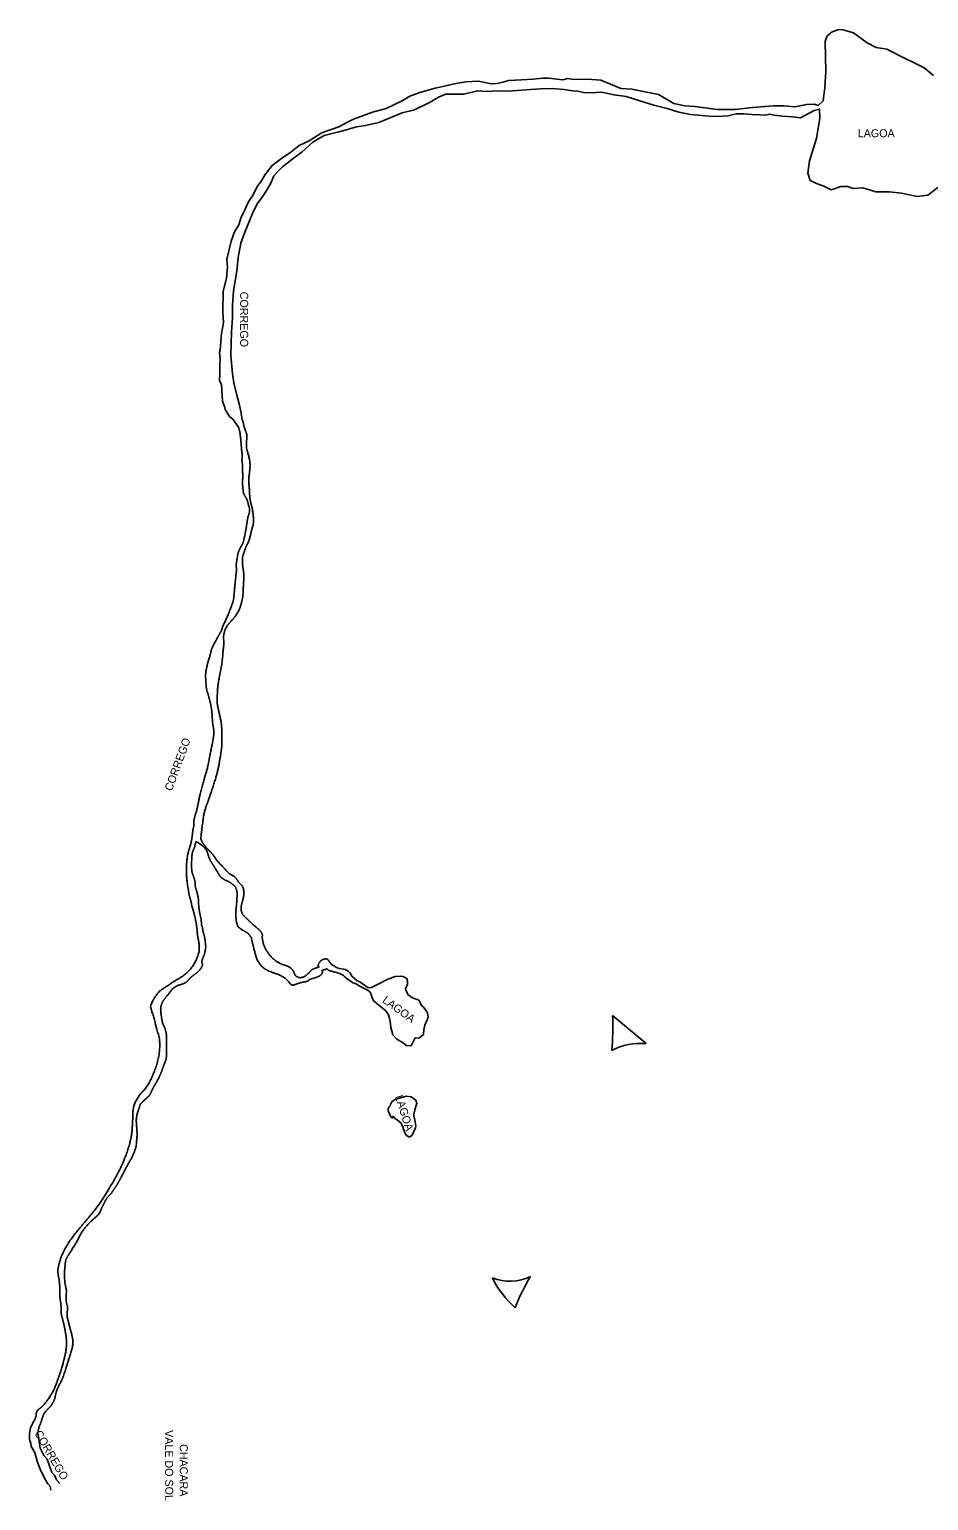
# Model space of a CAD drawing. Extents: x 325899 to 363134, y 7578590 to 7592502.
# Drawn here: x 347127 to 347576, y 7586466 to 7587201 of the extents above; entities that cross this region are included whole.
import ezdxf

# ---------------------------------------------------------------- set-up
doc = ezdxf.new("R2010")
doc.units = 0
for name, color, linetype in [('EDIFIDENTIF', 7, 'Continuous'), ('EDIFOBRAEXIS', 7, 'Continuous'), ('EDIFOBRAPROJ', 7, 'Continuous')]:
    doc.layers.add(name, color=color, linetype=linetype)

msp = doc.modelspace()

# ---------------------------------------------------------------- linework, layer by layer
at = {"layer": 'EDIFOBRAEXIS'}
for points in [[(347281.39, 7587152.06), (347285.49, 7587154.24), (347288.85, 7587155.9), (347293.86, 7587157.71), (347298.22, 7587159.38), (347305.14, 7587161.14), (347313.05, 7587164.99), (347316.99, 7587167.39), (347322, 7587169.2), (347329.52, 7587171.35), (347334.93, 7587172.53), (347339.93, 7587173.73), (347344.89, 7587174.53), (347351.28, 7587174.85), (347357.64, 7587173.44), (347360.4, 7587173.73), (347363.48, 7587174.25), (347366.41, 7587175.1), (347372.7, 7587175.49), (347378.41, 7587175.75), (347383.32, 7587176.26), (347386.29, 7587176.35), (347393.39, 7587175.57), (347395.92, 7587176.16), (347398.88, 7587175.71), (347405.63, 7587175.84), (347412.37, 7587175.25), (347417.21, 7587173.4), (347422.29, 7587171.15), (347427.8, 7587170.91), (347441.22, 7587168.16), (347443.97, 7587166.52), (347448.78, 7587163.71), (347454.42, 7587162.51), (347459.35, 7587162.16), (347470.66, 7587160.63), (347479.27, 7587160.67), (347488.24, 7587161.65), (347498.5, 7587162.46), (347503.96, 7587162.58), (347509.35, 7587162.04), (347515.15, 7587163.16), (347518.93, 7587163.27), (347521, 7587162.68), (347523.48, 7587165.04), (347524.35, 7587171.66), (347524.78, 7587179.87), (347524.63, 7587186.88), (347524.46, 7587194.7), (347525.41, 7587197.46), (347527.98, 7587199.45), (347531.31, 7587200.69), (347533.42, 7587200.46), (347538.66, 7587198.94), (347545.45, 7587193.99), (347549.89, 7587191.7), (347555.22, 7587190.9), (347563.74, 7587186.52), (347568.52, 7587184.14), (347573.98, 7587181.49), (347578.51, 7587177.73)], [(347580.68, 7587121.76), (347575.81, 7587117.79), (347570.42, 7587117.19), (347562.66, 7587118.82), (347556.35, 7587119.47), (347549.8, 7587119.46), (347543.21, 7587121.5), (347538.46, 7587121.26), (347535.83, 7587122.15), (347532.2, 7587122.14), (347527.43, 7587120.49), (347523.73, 7587122.39), (347520.1, 7587123.63), (347516.92, 7587125.18), (347515.8, 7587128.89), (347516.63, 7587135.03), (347520.17, 7587146.1), (347521.23, 7587153.39), (347521.87, 7587156.35), (347521.62, 7587160.89), (347518.99, 7587160.14), (347512.12, 7587156.46), (347508.22, 7587157.04), (347503.16, 7587157.33), (347498.91, 7587157.88), (347496.79, 7587158.26), (347494.57, 7587157.86), (347491.8, 7587157.97), (347487.86, 7587158.17), (347483.84, 7587158.56), (347480, 7587158.43), (347476.06, 7587157.53), (347473.12, 7587157.31), (347467.97, 7587157.25), (347462.78, 7587157.74), (347457.13, 7587158.25), (347451.39, 7587159.29), (347445.43, 7587161.17), (347438.85, 7587162.78), (347432.28, 7587164.77), (347425.09, 7587167.12), (347418.95, 7587167.98), (347412.73, 7587169.31), (347407, 7587169.01), (347403.69, 7587169.09), (347400.94, 7587169.77), (347398.41, 7587170.07), (347393.96, 7587170.68), (347388.26, 7587171.24), (347382.17, 7587170.98), (347377.25, 7587170.62), (347366.07, 7587169.81), (347360.78, 7587170.05), (347355.43, 7587169.63), (347350.81, 7587169.93), (347343.86, 7587168.39), (347334.97, 7587168.27), (347331.6, 7587166.97), (347326.73, 7587164.15), (347319.22, 7587160.56), (347313.08, 7587159.03), (347301.48, 7587154.15), (347294.84, 7587152.61), (347290.28, 7587151.97), (347288.55, 7587151.54), (347286.77, 7587151.03), (347285.97, 7587150.74), (347281.39, 7587149.51)], [(347281.39, 7587152.06), (347273.73, 7587149.29), (347272.58, 7587148.78), (347269.03, 7587146.44), (347266.61, 7587145.08), (347261.64, 7587142.65), (347257.48, 7587139.43), (347252.89, 7587136.2), (347248.19, 7587132.67), (347244.59, 7587128.26), (347242.46, 7587124.48), (347240.74, 7587122.16), (347238.46, 7587117.76), (347236.48, 7587114.85), (347234.95, 7587111.7), (347233.95, 7587109.39), (347232.62, 7587106.87), (347231.5, 7587103.05), (347229.3, 7587099.55), (347227.63, 7587094.81), (347225.5, 7587085.95), (347225.76, 7587081.9), (347225.38, 7587076.36), (347223.74, 7587069.96), (347223.71, 7587067.65), (347223.5, 7587061.42), (347223.49, 7587059.62), (347223.87, 7587054.05), (347222.85, 7587048.79), (347222.69, 7587047.09), (347222.43, 7587044.65), (347222.18, 7587040.64), (347221.79, 7587039.42), (347222.16, 7587035.98), (347222.02, 7587033.21), (347221.94, 7587028.46), (347221.83, 7587025.28), (347222.81, 7587023.07), (347223.35, 7587014.85), (347224.56, 7587011.67)], [(347234.23, 7587001.91), (347233.68, 7587004.43), (347233.15, 7587005.7), (347232.53, 7587009.72), (347231.63, 7587013.62), (347230.46, 7587017.95), (347229.02, 7587024.05), (347228.35, 7587028.58), (347227.45, 7587037.74), (347227.84, 7587049.58), (347228.28, 7587056.52), (347228.31, 7587062.8), (347228.9, 7587070.02), (347230.48, 7587079.87), (347231.25, 7587086.63), (347232.55, 7587093.87), (347234.54, 7587099.3), (347237.21, 7587105.87), (347238.91, 7587109.91), (347241.04, 7587113.99), (347242.37, 7587115.63), (347243.8, 7587117.79), (347244.88, 7587119.44), (347247.52, 7587123.82), (347249.06, 7587127.52), (347251.31, 7587130.06), (347253.3, 7587132.05), (347258.69, 7587136.22), (347263.12, 7587139.56), (347268.54, 7587144.34), (347271.78, 7587146.41), (347273.3, 7587147.24), (347274.2, 7587147.67), (347278.88, 7587148.86), (347281.39, 7587149.51)], [(347224.56, 7587011.67), (347224.69, 7587010.66), (347224.96, 7587010.17), (347226.45, 7587007.8), (347226.9, 7587007.23), (347228.64, 7587005.79), (347231.33, 7587001.91)], [(347281.39, 7586731.39), (347283.81, 7586731.13), (347284.6, 7586730.93), (347285.22, 7586730.62), (347286.1, 7586730.09), (347287.06, 7586729.09), (347288.03, 7586727.63), (347290.68, 7586725.23), (347292.01, 7586724.68), (347294.35, 7586723.08), (347296.17, 7586721.74), (347297.86, 7586721.97), (347300.46, 7586723.32), (347305.57, 7586725.89), (347309.69, 7586727.34), (347312.48, 7586727.53), (347313.6, 7586727.46), (347315.64, 7586726.23), (347315.66, 7586725.55), (347315.83, 7586725.15), (347315.84, 7586723.95), (347315.85, 7586723.5), (347315.5, 7586722.75), (347314.83, 7586721.18), (347315, 7586720.62), (347315.44, 7586719.7), (347315.96, 7586718.37), (347317.94, 7586716.98), (347319.07, 7586716.33), (347320.58, 7586715.95), (347321.36, 7586715.51), (347322.99, 7586712.77), (347323.88, 7586711.96), (347325.72, 7586709.25), (347326.04, 7586707.05), (347325.65, 7586705.71), (347324.44, 7586703.13), (347323.97, 7586700.96), (347323.75, 7586698.36), (347321.41, 7586696.61), (347319.66, 7586696.79), (347317.6, 7586692.76), (347315.23, 7586692.97), (347313.23, 7586694.35), (347310.38, 7586696.17), (347308.43, 7586698.32), (347307.43, 7586701.84), (347307.03, 7586704.96), (347306.81, 7586706.45), (347306.34, 7586708.31), (347304.96, 7586710.2), (347301.34, 7586713.21), (347298.84, 7586715.17), (347297.94, 7586717.17), (347297.69, 7586718.48), (347297.5, 7586719.06), (347296.37, 7586720.22), (347294.79, 7586721.14), (347291.36, 7586722.96), (347290.47, 7586723.57), (347288.67, 7586724.3), (347285.77, 7586726.12), (347284.45, 7586727.21), (347283.76, 7586727.94), (347282.97, 7586728.42), (347281.39, 7586729.01)], [(347318.15, 7586648.09), (347318.15, 7586648.09), (347318.15, 7586648.09), (347316.83, 7586647.16), (347315.31, 7586647.88), (347314.59, 7586648.97), (347314.15, 7586650.2), (347313.65, 7586651.48), (347313.53, 7586652.06), (347313.18, 7586652.77), (347312.63, 7586654.09), (347310.62, 7586655.86), (347309.4, 7586656.51), (347308.53, 7586657.6), (347308.08, 7586656.59), (347307.5, 7586657.24), (347306.19, 7586660.3), (347306.16, 7586661.23), (347306.66, 7586662.22), (347307.15, 7586662.82), (347307.31, 7586663.38), (347307.87, 7586664.79), (347308.57, 7586665.2), (347309.34, 7586665.73), (347311.15, 7586666.39), (347314.02, 7586667.3), (347315.11, 7586667.53), (347317.68, 7586667.26), (347319.94, 7586665.58), (347320.48, 7586663.94), (347320.05, 7586662.94), (347319.43, 7586660.83), (347318.96, 7586658.66), (347318.97, 7586657.72), (347319.39, 7586655.55), (347319.64, 7586654.82), (347319.86, 7586652.85), (347319.73, 7586651.85), (347318.15, 7586648.09)], [(347127.36, 7586501.91), (347126.94, 7586499.08), (347126.87, 7586498.07), (347126.9, 7586497.65), (347126.95, 7586496.05), (347127.19, 7586495.01), (347127.56, 7586494.1), (347127.79, 7586492.5), (347128.88, 7586490.69), (347129.77, 7586488.92), (347130.69, 7586485.22), (347131.85, 7586482.11), (347132.8, 7586480.08), (347133.45, 7586478.87), (347134.58, 7586476.45), (347135.99, 7586473.92), (347137.25, 7586472.64), (347137.56, 7586470.74)], [(347131.5, 7586501.91), (347131.21, 7586500.44), (347131.13, 7586499.39), (347131.14, 7586498.76), (347131.48, 7586497.46), (347131.82, 7586495), (347132.2, 7586491.78), (347134.11, 7586488.09), (347135.69, 7586486.23), (347137.99, 7586479.55), (347139.44, 7586478.14), (347140.38, 7586475.94), (347142.12, 7586473.98)]]:
    msp.add_lwpolyline(points, dxfattribs=at)
for points in [[(347231.33, 7587001.91), (347232.07, 7586999.5), (347232.15, 7586998.31), (347232.25, 7586997.34), (347232.55, 7586995.22), (347232.59, 7586993.78), (347232.82, 7586991.73), (347232.87, 7586990.64), (347233.07, 7586989.01), (347233.24, 7586986.72), (347232.85, 7586985.53), (347233.1, 7586985.15), (347233.3, 7586983.42), (347233.3, 7586981.51), (347233.32, 7586979.58), (347233.52, 7586978.52), (347233.51, 7586976.99), (347233.22, 7586974.02), (347233.54, 7586971.27), (347233.77, 7586969.21), (347233.79, 7586968.98), (347234.14, 7586968.09), (347235.48, 7586966.13), (347236.84, 7586961.4), (347236.94, 7586959.62), (347235.91, 7586956.78), (347235.21, 7586951.49), (347234.33, 7586947.3), (347233.69, 7586944.08), (347231.34, 7586940.1), (347230.69, 7586936.69), (347230.07, 7586932.63), (347230.45, 7586931.13), (347229.56, 7586923.51), (347229.08, 7586917.51), (347228.9, 7586915.68), (347226.64, 7586909.18), (347223.83, 7586903.19), (347222.52, 7586899.59), (347222.16, 7586899.18), (347220.65, 7586896.37), (347218.48, 7586892.48), (347217.67, 7586890.44), (347217.35, 7586888.51), (347215.81, 7586883.7), (347214.78, 7586878.82), (347215.07, 7586874.22), (347215.29, 7586870.99), (347216.25, 7586868.17), (347217.5, 7586863.16), (347218.05, 7586860.08), (347218.34, 7586853.88), (347219.11, 7586850.4), (347218.8, 7586845.98), (347217.28, 7586839.37), (347215.96, 7586831.88), (347214.39, 7586826.88), (347212, 7586818.14), (347210.66, 7586811.01), (347208.91, 7586805.5), (347209.11, 7586802.8), (347208.44, 7586800.42), (347208.09, 7586795.89), (347206.81, 7586791.35), (347206.01, 7586788.86), (347205.39, 7586784.67), (347205.27, 7586779.59), (347205.49, 7586775.9), (347206.63, 7586768.04), (347207.72, 7586764.58), (347207.89, 7586763.19), (347209.62, 7586757.18), (347210.57, 7586751.84), (347210.89, 7586747.34), (347211.74, 7586743.71), (347211.75, 7586739.26), (347209.22, 7586733.35), (347205.22, 7586728.63), (347199.08, 7586724.99), (347195.51, 7586722.46), (347191.24, 7586719.83), (347187.33, 7586713.31), (347187.55, 7586711.33), (347189.01, 7586707.08), (347190.31, 7586701.41), (347191.5, 7586698), (347192.2, 7586693.57), (347191.33, 7586685.65), (347188.74, 7586678.49), (347185.96, 7586672.55), (347181.44, 7586667.76), (347178.55, 7586662.33), (347178.48, 7586654.84), (347177.77, 7586645.97), (347173.69, 7586633.83), (347167.07, 7586621.83), (347160.56, 7586611.81), (347155.43, 7586605.71), (347147.98, 7586596.96), (347143.13, 7586588.79), (347140.89, 7586581.18), (347141.19, 7586578.79), (347142.11, 7586573.14), (347141.99, 7586567.47), (347142.67, 7586563.38), (347142.71, 7586560.02), (347142.88, 7586557.99), (347143.43, 7586556.41), (347144.64, 7586550.97), (347145.43, 7586546.04), (347145.31, 7586540.37), (347143.05, 7586531.61), (347140.61, 7586524.73), (347138.9, 7586520.11), (347134, 7586512.93), (347130.79, 7586510.71), (347130.25, 7586509.06), (347130.24, 7586507.99), (347129.88, 7586506.67), (347127.36, 7586501.91)], [(347234.23, 7587001.91), (347235.3, 7586998.92), (347235.47, 7586998.28), (347235.58, 7586997.46), (347235.32, 7586994.43), (347235.26, 7586991.62), (347235.84, 7586989.64), (347236.99, 7586985.19), (347237.19, 7586982.19), (347236.3, 7586975.25), (347236.77, 7586971.8), (347236.96, 7586966.31), (347237.64, 7586963.46), (347238.44, 7586960.28), (347239.03, 7586954.35), (347237.72, 7586949.94), (347236.66, 7586945.14), (347234.77, 7586941.51), (347233.95, 7586938.87), (347233.26, 7586936.89), (347233.35, 7586933), (347233.65, 7586931.22), (347234.05, 7586928.27), (347233.93, 7586924.97), (347233.75, 7586922.17), (347233.61, 7586918.74), (347233.48, 7586916.86), (347232.27, 7586912.06), (347230.83, 7586908.84), (347228.74, 7586906.15), (347225.07, 7586902.22), (347223.66, 7586897.4), (347224.21, 7586894.14), (347223.69, 7586891.32), (347223.29, 7586884.95), (347222.05, 7586878.65), (347220.96, 7586872.68), (347220.77, 7586868.28), (347220.55, 7586863.99), (347221.68, 7586859.11), (347222.84, 7586853.97), (347222.97, 7586850.47), (347223.16, 7586843.24), (347222.43, 7586838.44), (347221.19, 7586830.92), (347219.31, 7586824.27), (347216.65, 7586816.58), (347215.85, 7586814.07), (347214.85, 7586811.78), (347213.85, 7586807.49), (347213.4, 7586803.81), (347212.44, 7586796.69), (347212.84, 7586794.96), (347215.22, 7586791.68), (347218.06, 7586789.03), (347221.09, 7586784.54), (347223.76, 7586782.02), (347226.87, 7586778.53), (347229.87, 7586777.2), (347231.38, 7586774.4), (347234.09, 7586771.77), (347233.95, 7586766.76), (347232.62, 7586763.06), (347232.73, 7586758.86), (347236.08, 7586755.75), (347237.52, 7586754.33), (347241.88, 7586750.55), (347243.42, 7586748.64), (347243.09, 7586746.58), (347244.09, 7586742.44), (347246.87, 7586737.83), (347251.18, 7586734.13), (347256.08, 7586732.54), (347258.44, 7586731.03), (347259.32, 7586728.59), (347260.03, 7586727.49), (347262.19, 7586726.57), (347264.96, 7586727.63), (347266.92, 7586729.68), (347268.12, 7586730.95), (347270.18, 7586731.76), (347271.53, 7586732.06), (347271.63, 7586732.06), (347270.92, 7586733.13), (347272.46, 7586735.49), (347274.37, 7586736.27), (347275.97, 7586736.06), (347277.18, 7586734.25), (347277.56, 7586733.59), (347277.56, 7586733.56), (347281.39, 7586731.39)], [(347131.5, 7586501.91), (347132.7, 7586504.58), (347133.03, 7586505.97), (347133.5, 7586507.27), (347133.85, 7586508.33), (347134.34, 7586509.35), (347135.62, 7586510.77), (347137.27, 7586512.44), (347138.27, 7586513.79), (347139.44, 7586516.02), (347139.83, 7586517.92), (347140.14, 7586519.24), (347141.06, 7586522.06), (347142.65, 7586524.57), (347144.11, 7586528.35), (347145.44, 7586532.67), (347147.32, 7586538.64), (347148.75, 7586543.49), (347148.41, 7586547.1), (347147.1, 7586551.83), (347146.1, 7586555.82), (347145.52, 7586558.57), (347146.12, 7586561.64), (347145.49, 7586563.85), (347145.29, 7586564.62), (347145.27, 7586566.62), (347145.27, 7586568.45), (347145.38, 7586570.46), (347145.16, 7586571.58), (347144.66, 7586573.87), (347144.39, 7586577.2), (347144.37, 7586579.84), (347144.74, 7586583.6), (347144.95, 7586585.89), (347147.02, 7586589.24), (347150.44, 7586594.61), (347152.69, 7586599.21), (347155.57, 7586603.06), (347158.53, 7586605.85), (347161, 7586608), (347162.41, 7586610.11), (347163.12, 7586612.21), (347163.28, 7586612.29), (347164.4, 7586614.5), (347165.19, 7586616.02), (347165.55, 7586616.73), (347167.62, 7586618.73), (347169.15, 7586621.14), (347170.43, 7586622.94), (347171.75, 7586625.3), (347173.29, 7586628.12), (347175.97, 7586633.37), (347178.2, 7586637.05), (347180.22, 7586642.12), (347180.41, 7586645.17), (347180.72, 7586648.68), (347180.48, 7586652.01), (347180.16, 7586656), (347180.96, 7586659.78), (347181.7, 7586661.56), (347182.12, 7586663.57), (347184.1, 7586665.47), (347186.93, 7586667.95), (347187.67, 7586669.65), (347188.8, 7586672.01), (347189.64, 7586673.3), (347190.97, 7586675.76), (347192.56, 7586678.93), (347193.86, 7586682.64), (347194.76, 7586684.9), (347195.22, 7586686.3), (347195.36, 7586687.97), (347195.31, 7586690.92), (347195.3, 7586693.46), (347195.49, 7586697.88), (347194.69, 7586701.5), (347193.4, 7586703.79), (347192.85, 7586707.12), (347192.38, 7586710.6), (347192.56, 7586712.76), (347193.71, 7586715.55), (347196.03, 7586718.11), (347198.05, 7586721), (347200.27, 7586722.65), (347205.51, 7586724.46), (347207.06, 7586726.64), (347208.8, 7586728.01), (347210.58, 7586729.25), (347212.44, 7586731.23), (347213.08, 7586732.39), (347213.41, 7586733.36), (347212.91, 7586735.04), (347213.42, 7586736.33), (347213.55, 7586736.71), (347214.32, 7586738.44), (347214.68, 7586740.29), (347214.94, 7586741.54), (347214.94, 7586743.11), (347214.65, 7586745.5), (347214.07, 7586748.55), (347213.67, 7586749.32), (347213.39, 7586751.81), (347212.76, 7586753.36), (347212.77, 7586755.65), (347212.17, 7586758.06), (347211.62, 7586761.01), (347211.35, 7586763.94), (347211.35, 7586766), (347211, 7586767.65), (347210.55, 7586769.86), (347209.72, 7586772.2), (347209.63, 7586774.9), (347209.03, 7586777.06), (347207.87, 7586780.04), (347207.91, 7586785.47), (347208.07, 7586787.79), (347208.33, 7586789.69), (347209.33, 7586791.8), (347209.69, 7586793.24), (347209.94, 7586794.36), (347210.07, 7586794.72), (347210.61, 7586794.69), (347212.91, 7586793.06), (347213.52, 7586792.65), (347215.52, 7586790.56), (347216.8, 7586786.03), (347218.17, 7586783.92), (347219.33, 7586782.03), (347219.74, 7586781.45), (347221.38, 7586778.67), (347222.24, 7586777.17), (347224.5, 7586775.56), (347226.28, 7586775.02), (347229.44, 7586772.73), (347229.93, 7586771.86), (347230.66, 7586769.82), (347230.62, 7586767.87), (347230.52, 7586765.5), (347230.3, 7586762.76), (347230.1, 7586761.26), (347229.91, 7586758.26), (347230.33, 7586753.89), (347231.59, 7586751.65), (347233.92, 7586750.25), (347236.18, 7586748.99), (347237.32, 7586747.26), (347237.75, 7586747.08), (347237.97, 7586745.25), (347238.53, 7586743.39), (347239.63, 7586738.87), (347240.82, 7586735.08), (347244.13, 7586731.05), (347250.71, 7586728.51), (347253.09, 7586727.67), (347256.08, 7586725.4), (347257.58, 7586722.98), (347259.64, 7586723.3), (347262.18, 7586724.39), (347266.32, 7586725.06), (347266.56, 7586725.85), (347268.11, 7586726.33), (347269.94, 7586726.85), (347271.03, 7586727.28), (347272.36, 7586727.96), (347273.43, 7586729.44), (347273.05, 7586730.43), (347273.41, 7586730.58), (347275.42, 7586731.16), (347275.57, 7586731.31), (347276.23, 7586730.44), (347276.38, 7586730.54), (347281.39, 7586729.01)]]:
    msp.add_open_spline(points, degree=2, dxfattribs=at)
at = {"layer": 'EDIFOBRAPROJ'}
msp.add_lwpolyline([(347434.98, 7586693.85), (347418.26, 7586707.93)], dxfattribs=at)
for centre, radius, start, end in [((347282.17, 7586702.24), 136.21, 355.02164, 2.39641), ((347432.06, 7586663.95), 30.04, 84.43435, 118.22053), ((347366.84, 7586599.31), 24.17, 249.03775, 295.44479), ((347401.05, 7586597.89), 47.79, 206.27232, 228.85679), ((347452.66, 7586530.94), 88.64, 148.32767, 159.55699)]:
    msp.add_arc(centre, radius, start, end, dxfattribs=at)

# ---------------------------------------------------------------- texts
at = {"layer": 'EDIFIDENTIF'}
for s, rotation, p in [('LAGOA', 359.70333, (347540.73, 7587146.85)), ('CORREGO', 270, (347232.16, 7587069.6)), ('CORREGO', 70.05245, (347198.02, 7586819.76)), ('LAGOA', 323.99101, (347302.84, 7586714.84)), ('LAGOA', 287.53667, (347309.51, 7586667.42)), ('CORREGO', 300.10024, (347129.25, 7586499.2)), ('VALE DO SOL', 270.23119, (347194.6, 7586500.71)), ('CHACARA', 270, (347202, 7586493.73))]:
    msp.add_text(s, height=4, rotation=rotation, dxfattribs=at).set_placement(p)

doc.saveas('drawing.dxf')
